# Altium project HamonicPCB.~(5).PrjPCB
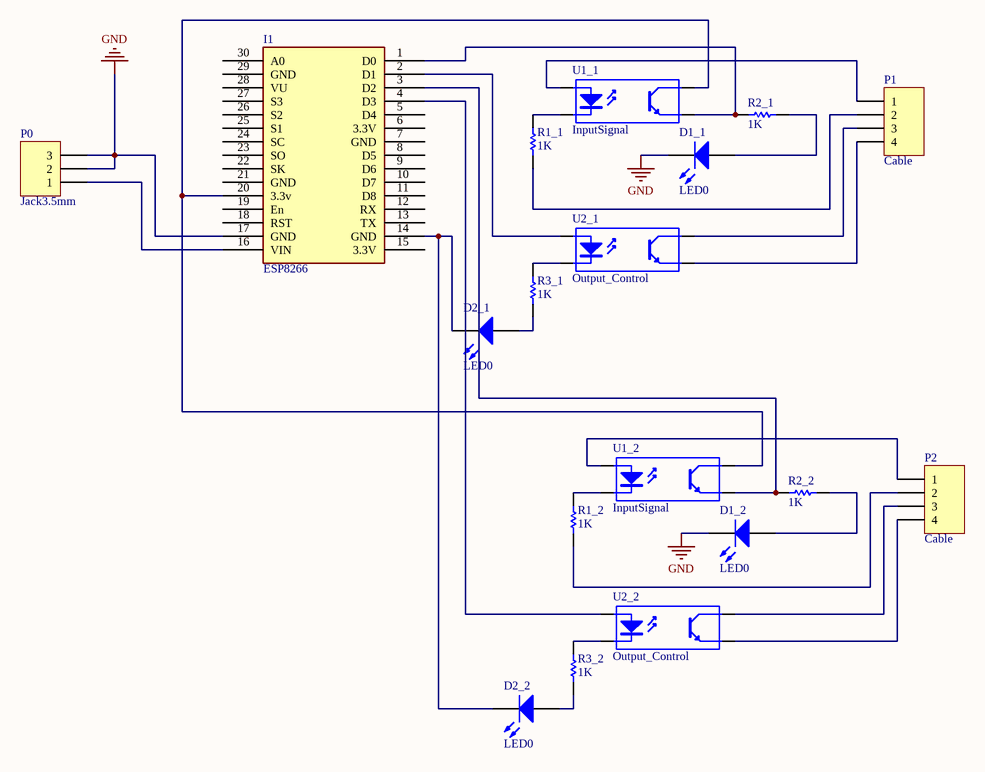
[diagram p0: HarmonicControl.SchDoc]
1 sheet, 18 parts. Net scope: global (net labels, ports and power ports of the same name join across sheets).
Board files: HarmonicControl.PcbDoc, HarmonicControl_2.PcbDoc

## Sheet HarmonicControl.SchDoc
size A

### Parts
D1_1  LED0  [LED-0]
D1_2  LED0  [LED-0]
D2_1  LED0  [LED-0]
D2_2  LED0  [LED-0]
I1  ESP8266  [ESP8266_Node_MCU_V3]
P0  Jack3.5mm  [HDR1X3]
P1  Cable  [HDR1X4]
P2  Cable  [HDR1X4]
R1_1  value 1K  [AXIAL-0.3]  (hidden comment: Res1)
R1_2  value 1K  [AXIAL-0.3]  (hidden comment: Res1)
R2_1  value 1K  [AXIAL-0.3]  (hidden comment: Res1)
R2_2  value 1K  [AXIAL-0.3]  (hidden comment: Res1)
R3_1  value 1K  [AXIAL-0.3]  (hidden comment: Res1)
R3_2  value 1K  [AXIAL-0.3]  (hidden comment: Res1)
U1_1  InputSignal  [DIP-4]
U1_2  InputSignal  [DIP-4]
U2_1  Output_Control  [DIP-4]
U2_2  Output_Control  [DIP-4]

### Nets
GND: D1_1.2(K) D1_2.2(K) I1.17(GND) P0.2 P0.3
NetD1_1_1: D1_1.1(A) R2_1.2
NetD1_2_1: D1_2.1(A) R2_2.2
NetD2_1_1: D2_1.1(A) R3_1.1
NetD2_1_2: D2_1.2(K) D2_2.2(K) I1.14(GND)
NetD2_2_1: D2_2.1(A) R3_2.1
NetI1_1: I1.1(D0) R2_1.1 U1_1.3(E)
NetI1_2: I1.2(D1) U2_1.1(A)
NetI1_3: I1.3(D2) R2_2.1 U1_2.3(E)
NetI1_4: I1.4(D3) U2_2.1(A)
NetI1_16: I1.16(VIN) P0.1
NetI1_20: I1.20(3.3v) U1_1.4(C) U1_2.4(C)
NetP1_1: P1.1 U1_1.1(A)
NetP1_2: P1.2 R1_1.1
NetP1_3: P1.3 U2_1.4(C)
NetP1_4: P1.4 U2_1.3(E)
NetP2_1: P2.1 U1_2.1(A)
NetP2_2: P2.2 R1_2.1
NetP2_3: P2.3 U2_2.4(C)
NetP2_4: P2.4 U2_2.3(E)
NetR1_1_2: R1_1.2 U1_1.2(K)
NetR1_2_2: R1_2.2 U1_2.2(K)
NetR3_1_2: R3_1.2 U2_1.2(K)
NetR3_2_2: R3_2.2 U2_2.2(K)

Not connected (* = marked no-connect by the designer): I1 5(D4) 6(3.3V) 7(GND) 8(D5) 9(D6) 10(D7) 11(D8) 12(RX) 13(TX) 15(3.3V) 18(RST) 19(En) 21(GND) 22(SK) 23(SO) 24(SC) 25(S1) 26(S2) 27(S3) 28(VU) 29(GND) 30(A0)

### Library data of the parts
D1_1 D1_2 D2_1 D2_2 = LED0: Typical INFRARED GaAs LED
I1 = ESP8266_Node_MCU_V3
P0 = Header 3: Header, 3-Pin
P1 P2 = Header 4: Header, 4-Pin
R1_1 R1_2 R2_1 R2_2 R3_1 R3_2 = Res1: Resistor
U1_1 U1_2 U2_1 U2_2 = Optoisolator1: 4-Pin Phototransistor Optocoupler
